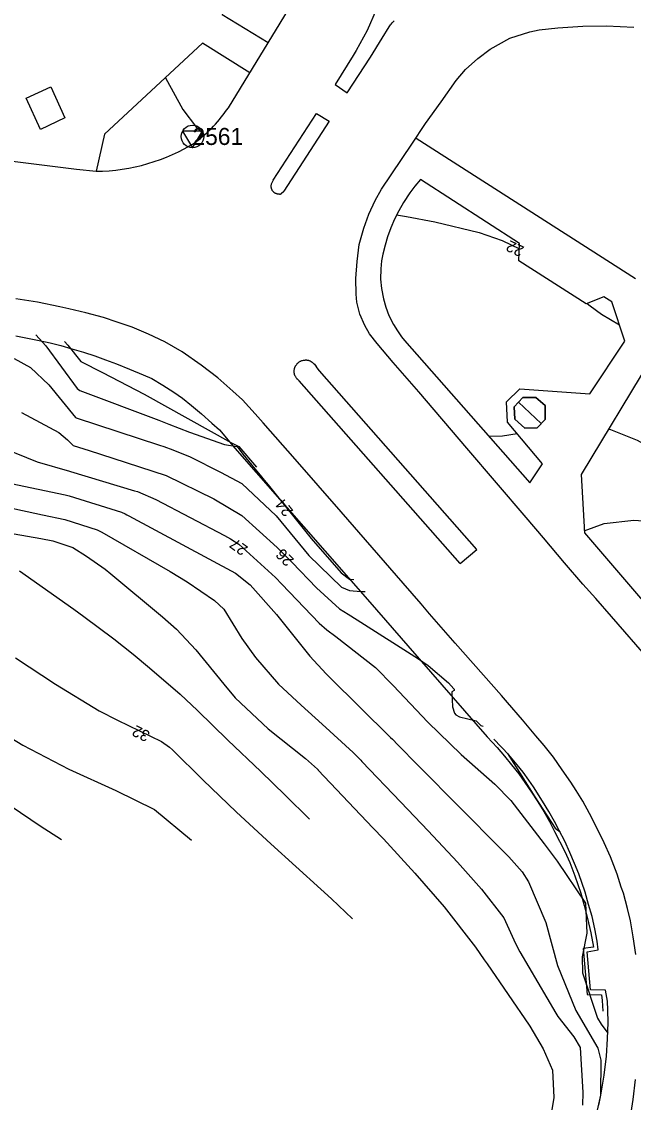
# Model space of a CAD drawing. Extents: x 67169 to 69652, y 20189 to 22818.
# Drawn here: x 69374.5 to 69428.4, y 21050.3 to 21145.5 of the extents above; entities that cross this region are included whole.
import ezdxf

# ---------------------------------------------------------------- set-up
doc = ezdxf.new("R2010")
doc.units = 0
for name, color, linetype in [('BYGGNAD_HUSLIV', 7, 'Continuous'), ('BYGGNADSSYMBOLER', 7, 'Continuous'), ('HOJDKURVOR_2014', 7, 'Continuous'), ('HOJDKURVOR_2014 5M', 7, 'Continuous'), ('HOJDKURVOR_TEXTER_2014', 7, 'Continuous'), ('MUR_STAKET', 7, 'Continuous'), ('MUR_STAKET_SYMBOL', 7, 'Continuous'), ('Std_Ritningsstämpel', 7, 'Continuous'), ('STOMPUNKTER', 7, 'Continuous'), ('STOMPUNKTER TEXT', 7, 'Continuous'), ('VAGAR 121', 7, 'Continuous'), ('VAGAR 123', 7, 'Continuous')]:
    doc.layers.add(name, color=color, linetype=linetype)

msp = doc.modelspace()

# ---------------------------------------------------------------- linework, layer by layer
at = {"layer": 'BYGGNAD_HUSLIV'}
for points in [[(69374.902, 21138.738), (69377.059, 21139.754), (69378.31, 21137.01), (69376.153, 21135.994), (69374.902, 21138.738)], [(69418.636, 21112.366), (69419.777, 21112.379), (69420.577, 21111.661), (69420.59, 21110.437), (69419.885, 21109.706), (69418.803, 21109.669), (69417.908, 21110.469), (69417.871, 21111.541), (69418.636, 21112.366)]]:
    msp.add_lwpolyline(points, dxfattribs=at)
at = {"layer": 'BYGGNADSSYMBOLER'}
msp.add_line((69418.254, 21111.954), (69420.238, 21110.071), dxfattribs=at)
at = {"layer": 'HOJDKURVOR_2014'}
for points in [[(69387.149, 21140.542), (69388.696, 21137.747), (69389.902, 21136.161), (69390.587, 21135.518)], [(69407.508, 21128.455), (69408.384, 21128.315), (69410.882, 21127.86), (69414.767, 21126.915), (69416.793, 21126.201), (69418.318, 21125.48)], [(69424.29, 21120.665), (69424.541, 21120.44), (69425.562, 21119.703), (69427.133, 21118.762)], [(69375.738, 21117.895), (69375.741, 21117.894), (69376.617, 21116.936), (69379.382, 21113.155), (69379.634, 21112.995), (69386.562, 21110.367), (69387.468, 21110.021), (69389.278, 21109.323), (69392.359, 21108.219), (69393.458, 21108.045), (69393.552, 21107.936), (69393.965, 21107.374), (69394.761, 21106.414), (69395.485, 21105.544), (69395.844, 21105.105), (69396.2, 21104.665), (69399.985, 21099.956), (69402.643, 21096.913), (69403.373, 21096.368), (69403.756, 21096.332)], [(69378.269, 21117.317), (69378.562, 21116.994), (69379.701, 21115.543), (69381.627, 21114.581), (69385.299, 21112.664), (69392.987, 21108.374), (69393.08, 21108.324), (69393.271, 21108.233), (69393.612, 21108.044), (69395.184, 21106.241)], [(69374.489, 21111.063), (69377.786, 21109.284), (69378.541, 21108.651), (69378.993, 21108.163), (69379.031, 21108.133), (69380.434, 21107.694), (69382.539, 21107.034), (69387.226, 21105.512), (69391.418, 21103.447), (69393.872, 21101.972), (69396.998, 21099.164), (69398.312, 21097.845), (69400.453, 21095.598), (69402.487, 21093.769), (69403.255, 21093.277), (69404.032, 21092.794), (69409.426, 21089.342), (69410.284, 21088.757), (69412.093, 21087.243), (69412.558, 21086.719), (69412.582, 21086.665), (69412.587, 21086.615), (69412.564, 21086.569), (69412.383, 21086.454), (69412.376, 21086.407), (69412.437, 21085.117), (69412.619, 21084.56), (69412.73, 21084.419), (69413.052, 21084.247), (69414.505, 21083.878), (69414.718, 21083.679), (69414.938, 21083.479), (69415.02, 21083.437), (69415.14, 21083.423)], [(69426.168, 21109.596), (69426.347, 21109.55), (69428.677, 21108.603), (69431.729, 21106.948), (69433.534, 21105.997), (69435.471, 21105.357), (69437.235, 21104.969), (69437.635, 21105.079), (69439.429, 21106.819)], [(69415.63, 21108.958), (69416.825, 21109.002), (69418.118, 21109.193)], [(69371.939, 21108.298), (69375.876, 21106.71), (69378.711, 21105.87), (69378.79, 21105.852), (69384.443, 21104.165), (69384.685, 21104.089), (69386.312, 21103.386), (69392.364, 21100.206), (69392.874, 21099.923), (69393.613, 21099.454), (69396.844, 21096.505), (69397.416, 21095.921), (69400.707, 21092.5), (69401.37, 21091.901), (69402.167, 21091.307), (69405.663, 21088.576), (69407.193, 21087.008), (69410.26, 21083.773), (69413.206, 21080.92), (69416.154, 21078.303), (69417.561, 21076.861), (69420.492, 21073.051), (69421.656, 21071.54), (69424.131, 21067.813), (69424.26, 21065.177), (69423.857, 21063.104), (69423.886, 21061.676), (69425.206, 21057.695), (69425.523, 21057.167), (69426.104, 21056.381)], [(69373.571, 21104.784), (69378.317, 21103.801), (69378.67, 21103.706), (69383.276, 21102.263), (69383.606, 21102.113), (69383.769, 21102.032), (69383.93, 21101.949), (69393.324, 21096.91), (69394.626, 21095.856), (69396.945, 21093.255), (69399.862, 21089.596), (69401.308, 21088.032), (69401.609, 21087.731), (69406.971, 21082.431), (69407.136, 21082.267), (69407.625, 21081.771), (69409.422, 21079.942), (69410.898, 21078.449), (69411.637, 21077.704), (69412.376, 21076.959), (69417.388, 21071.918), (69418.571, 21070.598), (69419.114, 21069.692), (69420.663, 21066.134), (69421.679, 21062.345), (69423.291, 21058.372), (69425.213, 21055.061), (69425.496, 21054.005), (69425.45, 21050.899), (69425.282, 21050.037)], [(69373.214, 21102.704), (69376.347, 21102.025), (69378.315, 21101.621), (69381.155, 21100.703), (69381.45, 21100.562), (69381.546, 21100.509), (69387.585, 21097.035), (69389.069, 21096.134), (69391.468, 21094.486), (69392.287, 21093.728), (69393.895, 21091.153)], [(69424.035, 21100.638), (69425.772, 21101.27), (69428.396, 21101.578), (69430.437, 21101.426), (69433.415, 21100.717), (69433.599, 21100.65), (69433.693, 21100.627), (69435.385, 21100.455)], [(69374.312, 21097.108), (69379.098, 21093.73), (69379.986, 21093.093), (69382.604, 21091.122), (69384.313, 21089.76), (69385.755, 21088.558), (69388.452, 21086.251), (69389.968, 21084.803), (69392.648, 21082.197), (69395.549, 21079.419), (69397.701, 21077.341), (69399.827, 21075.237)], [(69393.895, 21091.153), (69395.087, 21089.457), (69397.106, 21087.11), (69399.112, 21085.268), (69400.97, 21083.583), (69403.674, 21081.101), (69404.361, 21080.411), (69404.458, 21080.311), (69407.889, 21076.736), (69410.292, 21074.206), (69412.884, 21071.45), (69414.99, 21069.057), (69416.94, 21066.54), (69417.844, 21064.601), (69418.227, 21063.795), (69418.371, 21063.535), (69421.527, 21058.139), (69421.716, 21057.83), (69423.104, 21056.055), (69423.677, 21055.105), (69423.908, 21051.155), (69423.888, 21050.029)], [(69373.965, 21089.451), (69377.49, 21087.106), (69381.332, 21084.784), (69382.924, 21083.951), (69386.813, 21082.062), (69387.528, 21081.561), (69387.785, 21081.324), (69390.457, 21078.692), (69393.41, 21075.846), (69396.425, 21073.066), (69400.853, 21069.074), (69401.792, 21068.212), (69403.628, 21066.444)], [(69372.073, 21083.279), (69374.614, 21081.754), (69378.651, 21079.642), (69382.803, 21077.752), (69386.207, 21076.089), (69389.453, 21073.386)], [(69417.262, 21081.016), (69417.819, 21080.138), (69419.683, 21077.187), (69421.474, 21074.426), (69421.899, 21074.096)], [(69367.61, 21080.391), (69376.137, 21074.632), (69378.019, 21073.428)]]:
    msp.add_lwpolyline(points, dxfattribs=at)
at = {"layer": 'HOJDKURVOR_2014 5M'}
for points in [[(69373.848, 21115.82), (69375.29, 21115.029), (69376.88, 21113.48), (69379.247, 21110.606), (69379.309, 21110.572), (69386.622, 21108.184), (69387.02, 21108.05), (69387.813, 21107.77), (69389.326, 21107.137), (69392.019, 21105.809), (69393.882, 21104.792), (69396.903, 21101.96), (69399.789, 21098.468), (69402.661, 21095.679), (69403.353, 21095.38), (69404.364, 21095.297), (69404.737, 21095.278)], [(69371.97, 21100.693), (69376.198, 21099.942), (69377.252, 21099.746), (69378.996, 21099.155), (69380.217, 21098.398), (69381.837, 21097.249), (69382.354, 21096.835), (69386.891, 21093.055), (69388.129, 21091.951), (69389.844, 21090.149), (69392.289, 21087.106), (69393.307, 21085.923), (69396.191, 21083.18)], [(69396.191, 21083.18), (69399.491, 21080.571), (69400.554, 21079.621), (69400.601, 21079.571), (69400.617, 21079.554), (69405.418, 21074.474), (69406.352, 21073.48), (69409.126, 21070.474), (69411.691, 21067.507), (69414.449, 21063.954), (69415.233, 21062.84), (69415.492, 21062.467), (69419.186, 21057.087), (69419.243, 21057.002), (69420.405, 21054.98), (69421.232, 21053.119), (69421.358, 21050.715), (69421.013, 21048.538)]]:
    msp.add_lwpolyline(points, dxfattribs=at)
at = {"layer": 'MUR_STAKET'}
msp.add_lwpolyline([(69373.976, 21117.797), (69375.014, 21117.612), (69376.027, 21117.4), (69377.004, 21117.188), (69377.945, 21116.94), (69378.921, 21116.674), (69379.934, 21116.372), (69380.947, 21116.036), (69381.888, 21115.699), (69382.847, 21115.327), (69384.002, 21114.883), (69385.209, 21114.369), (69385.955, 21114.049), (69386.932, 21113.464), (69387.908, 21112.829), (69388.655, 21112.315), (69389.454, 21111.675), (69390.343, 21110.929), (69391.25, 21110.113), (69391.907, 21109.527), (69393.276, 21107.911), (69397.222, 21103.382), (69405.141, 21094.339), (69408.51, 21090.494), (69415.495, 21082.486), (69416.357, 21081.535), (69416.997, 21080.789), (69417.618, 21080.025), (69418.259, 21079.226), (69418.81, 21078.463), (69419.38, 21077.592), (69419.93, 21076.758), (69420.482, 21075.887), (69420.98, 21075.017), (69421.424, 21074.146), (69422.331, 21072.37), (69422.75, 21071.418), (69423.195, 21070.246), (69423.729, 21068.7), (69424.032, 21067.617), (69424.317, 21066.479), (69424.602, 21065.217), (69424.834, 21063.938), (69423.941, 21063.818), (69424.295, 21059.771), (69425.556, 21059.763), (69425.609, 21059.265), (69425.654, 21058.303)], dxfattribs=at)
at = {"layer": 'MUR_STAKET_SYMBOL'}
for p, q in [((69374.54, 21117.686), (69374.54, 21117.686)), ((69376.033, 21117.386), (69376.033, 21117.386)), ((69377.519, 21117.049), (69377.519, 21117.049)), ((69378.931, 21116.657), (69378.931, 21116.657)), ((69380.458, 21116.188), (69380.458, 21116.188)), ((69381.838, 21115.704), (69381.838, 21115.704)), ((69383.263, 21115.162), (69383.263, 21115.162)), ((69384.618, 21114.619), (69384.618, 21114.619)), ((69386.001, 21114.012), (69386.001, 21114.012)), ((69387.363, 21113.168), (69387.363, 21113.168)), ((69388.65, 21112.318), (69388.65, 21112.318)), ((69389.755, 21111.406), (69389.755, 21111.406)), ((69390.918, 21110.403), (69390.918, 21110.403)), ((69391.931, 21109.487), (69391.931, 21109.487)), ((69392.936, 21108.299), (69392.936, 21108.299)), ((69393.916, 21107.174), (69393.916, 21107.174)), ((69394.583, 21106.41), (69394.583, 21106.41)), ((69395.554, 21105.296), (69395.554, 21105.296)), ((69396.582, 21104.116), (69396.582, 21104.116)), ((69397.572, 21102.975), (69397.572, 21102.975)), ((69398.554, 21101.854), (69398.554, 21101.854)), ((69399.553, 21100.713), (69399.553, 21100.713)), ((69400.518, 21099.611), (69400.518, 21099.611)), ((69401.517, 21098.473), (69401.517, 21098.473)), ((69402.489, 21097.362), (69402.489, 21097.362)), ((69403.473, 21096.239), (69403.473, 21096.239)), ((69404.437, 21095.138), (69404.437, 21095.138)), ((69405.428, 21094.007), (69405.428, 21094.007)), ((69406.401, 21092.895), (69406.401, 21092.895)), ((69407.4, 21091.754), (69407.4, 21091.754)), ((69408.398, 21090.615), (69408.398, 21090.615)), ((69409.33, 21089.548), (69409.33, 21089.548)), ((69410.359, 21088.369), (69410.359, 21088.369)), ((69411.315, 21087.273), (69411.315, 21087.273)), ((69412.285, 21086.161), (69412.285, 21086.161)), ((69413.315, 21084.981), (69413.315, 21084.981)), ((69414.303, 21083.848), (69414.303, 21083.848)), ((69415.291, 21082.714), (69415.291, 21082.714)), ((69416.312, 21081.584), (69416.312, 21081.584)), ((69417.267, 21080.451), (69417.267, 21080.451)), ((69418.228, 21079.255), (69418.228, 21079.255)), ((69419.081, 21078.042), (69419.081, 21078.042)), ((69419.941, 21076.739), (69419.941, 21076.739)), ((69420.714, 21075.474), (69420.714, 21075.474)), ((69421.439, 21074.115), (69421.439, 21074.115)), ((69422.089, 21072.84), (69422.089, 21072.84)), ((69422.739, 21071.432), (69422.739, 21071.432)), ((69423.266, 21070.026), (69423.266, 21070.026)), ((69423.724, 21068.706), (69423.724, 21068.706)), ((69424.142, 21067.173), (69424.142, 21067.173)), ((69424.493, 21065.686), (69424.493, 21065.686)), ((69424.413, 21063.881), (69424.413, 21063.881)), ((69423.989, 21063.27), (69423.989, 21063.27)), ((69424.117, 21061.799), (69424.117, 21061.799)), ((69424.248, 21060.298), (69424.248, 21060.298)), ((69424.911, 21059.765), (69424.911, 21059.765)), ((69425.635, 21058.71), (69425.635, 21058.71))]:
    msp.add_line(p, q, dxfattribs=at)
at = {"layer": 'Std_Ritningsstämpel'}
msp.add_lwpolyline([(69418.636, 21112.366), (69417.871, 21111.541), (69417.908, 21110.469), (69418.803, 21109.669), (69419.885, 21109.706), (69420.59, 21110.437), (69420.577, 21111.661), (69419.777, 21112.379)], close=True, dxfattribs=at)
at = {"layer": 'STOMPUNKTER'}
msp.add_lwpolyline([(69389.538, 21134.37), (69390.415, 21135.85), (69388.663, 21135.85)], close=True, dxfattribs=at)
msp.add_circle((69389.538, 21135.37), 1, dxfattribs=at)
at = {"layer": 'VAGAR 121'}
for p, q in [((69392.699, 21137.902), (69398.326, 21147.084)), ((69409.228, 21135.23), (69428.554, 21122.844)), ((69413.109, 21097.748), (69398.924, 21113.835)), ((69413.109, 21097.748), (69414.573, 21098.989))]:
    msp.add_line(p, q, dxfattribs=at)
for points in [[(69405.72, 21146.536), (69404.91, 21144.697), (69403.937, 21142.945), (69403.694, 21142.496), (69402.093, 21139.952), (69403.163, 21139.204), (69405.201, 21142.358), (69406.236, 21144.037), (69406.855, 21145.02), (69406.919, 21145.117), (69406.979, 21145.199), (69407.034, 21145.269), (69407.134, 21145.389), (69407.291, 21145.563)], [(69429.758, 21089.277), (69426.435, 21093.071), (69425.046, 21094.653), (69423.917, 21095.932), (69422.303, 21097.808), (69420.446, 21099.997), (69418.905, 21101.808), (69413.682, 21107.922), (69409.457, 21112.875), (69407.22, 21115.466), (69405.787, 21117.125), (69405.124, 21117.982), (69404.7, 21118.708), (69404.287, 21119.717), (69404.016, 21120.78), (69403.939, 21121.462), (69403.927, 21122.862), (69404.045, 21124.348), (69404.228, 21125.845), (69404.639, 21127.3), (69405.072, 21128.526), (69405.624, 21129.73), (69406.177, 21130.718), (69408.864, 21134.69), (69410.066, 21136.513), (69411.431, 21138.434), (69412.753, 21140.312), (69413.577, 21141.279), (69414.672, 21142.245), (69415.734, 21143.07), (69417.48, 21144.026), (69419.237, 21144.581), (69420.072, 21144.755), (69421.71, 21144.941), (69423.901, 21145.094), (69425.995, 21145.106), (69428.382, 21144.989)], [(69396.65, 21131.528), (69400.471, 21137.407), (69401.562, 21136.724), (69397.57, 21130.545)], [(69343.935, 21136.014), (69354.15, 21135.295), (69359.697, 21134.83), (69361.215, 21134.703), (69363.993, 21134.363), (69365.617, 21134.151), (69369.658, 21133.684), (69379.34, 21132.474), (69381.049, 21132.304)], [(69396.65, 21131.528), (69396.48, 21131.164), (69396.472, 21131.145), (69396.465, 21131.128), (69396.46, 21131.111), (69396.456, 21131.095), (69396.45, 21131.064), (69396.446, 21131.036), (69396.444, 21131.012), (69396.444, 21130.991), (69396.444, 21130.953), (69396.446, 21130.925), (69396.449, 21130.905), (69396.453, 21130.874), (69396.459, 21130.844), (69396.464, 21130.822), (69396.476, 21130.781), (69396.488, 21130.747), (69396.5, 21130.717), (69396.512, 21130.692), (69396.524, 21130.67), (69396.534, 21130.651), (69396.555, 21130.618), (69396.572, 21130.594), (69396.6, 21130.558), (69396.63, 21130.523), (69396.642, 21130.51), (69396.665, 21130.487), (69396.686, 21130.469), (69396.704, 21130.454), (69396.72, 21130.442), (69396.734, 21130.432), (69396.76, 21130.415), (69396.78, 21130.404), (69396.795, 21130.396), (69396.819, 21130.384), (69396.844, 21130.373), (69396.879, 21130.36), (69396.909, 21130.35), (69396.936, 21130.342), (69396.959, 21130.336), (69397, 21130.327), (69397.03, 21130.322), (69397.076, 21130.315), (69397.122, 21130.309), (69397.137, 21130.307), (69397.166, 21130.304), (69397.192, 21130.3), (69397.215, 21130.298), (69397.235, 21130.297), (69397.253, 21130.296), (69397.268, 21130.297), (69397.281, 21130.298), (69397.292, 21130.299), (69397.301, 21130.301), (69397.309, 21130.304), (69397.322, 21130.308), (69397.332, 21130.313), (69397.339, 21130.317), (69397.348, 21130.323), (69397.357, 21130.331), (69397.57, 21130.545)], [(69424.511, 21112.706), (69427.6, 21117.323), (69426.47, 21120.8), (69425.767, 21121.246), (69424.213, 21120.635), (69418.259, 21124.418), (69418.344, 21125.954), (69409.607, 21131.575), (69409.121, 21130.99), (69408.679, 21130.398), (69408.124, 21129.539), (69407.701, 21128.832), (69407.321, 21128.089), (69406.995, 21127.31), (69406.713, 21126.523), (69406.496, 21125.789), (69406.311, 21124.993), (69406.187, 21124.401), (69406.118, 21123.72), (69406.101, 21122.81), (69406.173, 21121.97), (69406.344, 21121.077), (69406.557, 21120.326), (69406.84, 21119.601), (69407.247, 21118.797), (69407.592, 21118.232), (69407.937, 21117.728), (69408.217, 21117.396), (69419.245, 21104.842), (69420.347, 21106.532)], [(69428.584, 21063.303), (69428.348, 21064.868), (69428.113, 21066.259), (69427.844, 21067.369), (69427.48, 21068.7), (69427.282, 21069.249), (69426.918, 21070.371), (69426.332, 21071.901), (69425.793, 21073.128), (69425.033, 21074.704), (69424.494, 21075.732), (69423.897, 21076.819), (69423.323, 21077.741), (69422.844, 21078.488), (69422.095, 21079.586), (69421.311, 21080.683), (69420.504, 21081.723), (69419.767, 21082.576), (69418.608, 21083.965), (69417.275, 21085.518), (69416.736, 21086.125), (69412.677, 21090.726), (69410.419, 21093.318), (69409.67, 21094.206), (69408.079, 21096.027), (69402.627, 21102.298), (69398.591, 21106.933), (69395.761, 21110.144), (69395.07, 21110.937), (69393.935, 21112.164), (69393.105, 21112.945), (69391.783, 21114.101), (69390.309, 21115.234), (69388.625, 21116.401), (69387.094, 21117.276), (69385.667, 21117.965), (69384.241, 21118.56), (69382.896, 21119.014), (69381.704, 21119.41), (69380.149, 21119.841), (69378.665, 21120.178), (69377.858, 21120.364), (69375.894, 21120.761), (69374, 21121.074)], [(69442.143, 21111.211), (69433.972, 21116.298), (69429.889, 21115.752), (69423.754, 21105.602), (69424.046, 21100.444), (69430.752, 21092.649), (69433.374, 21096.69)], [(69398.924, 21113.835), (69398.809, 21113.947), (69398.798, 21113.959), (69398.777, 21113.98), (69398.762, 21113.997), (69398.741, 21114.022), (69398.719, 21114.048), (69398.699, 21114.074), (69398.681, 21114.097), (69398.667, 21114.118), (69398.643, 21114.155), (69398.626, 21114.184), (69398.602, 21114.228), (69398.579, 21114.274), (69398.564, 21114.306), (69398.552, 21114.335), (69398.543, 21114.36), (69398.535, 21114.382), (69398.523, 21114.421), (69398.515, 21114.45), (69398.51, 21114.473), (69398.503, 21114.506), (69398.498, 21114.541), (69398.495, 21114.564), (69398.494, 21114.584), (69398.493, 21114.602), (69398.493, 21114.634), (69398.493, 21114.658), (69398.495, 21114.693), (69398.498, 21114.729), (69398.506, 21114.809), (69398.515, 21114.869), (69398.523, 21114.914), (69398.53, 21114.947), (69398.537, 21114.972), (69398.548, 21115.009), (69398.561, 21115.047), (69398.576, 21115.081), (69398.591, 21115.111), (69398.604, 21115.136), (69398.617, 21115.157), (69398.64, 21115.194), (69398.658, 21115.22), (69398.686, 21115.26), (69398.715, 21115.301), (69398.729, 21115.319), (69398.741, 21115.335), (69398.762, 21115.362), (69398.779, 21115.381), (69398.792, 21115.396), (69398.803, 21115.406), (69398.819, 21115.422), (69398.837, 21115.437), (69398.869, 21115.461), (69398.899, 21115.483), (69398.928, 21115.502), (69398.983, 21115.534), (69399.031, 21115.56), (69399.075, 21115.579), (69399.113, 21115.595), (69399.181, 21115.619), (69399.233, 21115.634), (69399.311, 21115.653), (69399.389, 21115.667), (69399.447, 21115.675), (69399.498, 21115.678), (69399.544, 21115.679), (69399.584, 21115.678), (69399.619, 21115.675), (69399.65, 21115.672), (69399.703, 21115.663), (69399.743, 21115.653), (69399.772, 21115.645), (69399.816, 21115.63), (69399.858, 21115.612), (69399.897, 21115.592), (69399.93, 21115.575), (69399.959, 21115.559), (69399.983, 21115.545), (69400.024, 21115.518), (69400.055, 21115.497), (69400.077, 21115.481), (69400.11, 21115.455), (69400.142, 21115.428), (69400.175, 21115.398), (69400.2, 21115.376), (69400.218, 21115.359), (69400.231, 21115.346), (69400.25, 21115.326), (69400.259, 21115.316), (69400.267, 21115.305), (69400.428, 21115.099)], [(69414.573, 21098.989), (69400.735, 21114.729), (69400.427, 21115.1)], [(69425.066, 21049.068), (69425.485, 21050.911), (69425.782, 21052.666), (69425.991, 21054.334), (69426.092, 21055.882), (69426.126, 21057.303), (69426.108, 21058.392), (69426.072, 21059.181), (69425.895, 21060.164), (69424.58, 21060.181), (69424.298, 21063.532), (69425.261, 21063.708), (69425.156, 21064.481), (69424.962, 21065.568), (69424.716, 21066.639), (69424.416, 21067.709), (69424.1, 21068.786), (69423.555, 21070.418), (69423.186, 21071.313), (69422.764, 21072.295), (69422.307, 21073.295), (69421.833, 21074.224), (69421.412, 21075.032), (69420.92, 21075.891), (69420.358, 21076.821), (69419.563, 21078.061), (69419.16, 21078.666), (69418.642, 21079.376), (69418.132, 21080.017), (69417.384, 21080.889), (69416.058, 21082.272)], [(69428.152, 21049.386), (69428.349, 21050.531), (69428.546, 21052.284)]]:
    msp.add_lwpolyline(points, dxfattribs=at)
for centre, radius, start, end in [((69381.972, 21145.226), 12.988, 307.16947, 325.6766), ((69380.918, 21148.991), 16.688, 270.44895, 302.23689)]:
    msp.add_arc(centre, radius, start, end, dxfattribs=at)
at = {"layer": 'VAGAR 123'}
for points in [[(69391.494, 21166.95), (69389.364, 21164.878), (69392.161, 21146.113), (69396.212, 21143.635)], [(69394.582, 21140.975), (69390.427, 21143.594), (69381.796, 21135.558), (69381.049, 21132.304)], [(69420.347, 21106.532), (69417.27, 21110.207), (69417.18, 21111.993), (69418.363, 21113.144), (69424.511, 21112.706)]]:
    msp.add_lwpolyline(points, dxfattribs=at)

# ---------------------------------------------------------------- texts
at = {"layer": 'HOJDKURVOR_TEXTER_2014'}
for s, rotation, p in [('22', 154.67437, (69418.816, 21125.62)), ('24', 128.79302, (69398.469, 21102.385)), ('27', 144.23048, (69394.496, 21099.18)), ('26', 134.89142, (69398.538, 21098.1)), ('32', 154.09521, (69385.89, 21082.889))]:
    msp.add_text(s, height=1, rotation=rotation, dxfattribs=at).set_placement(p)
at = {"layer": 'STOMPUNKTER TEXT'}
msp.add_text('2561', height=1.5, dxfattribs=at).set_placement((69389.538, 21134.62))

doc.saveas('drawing.dxf')
